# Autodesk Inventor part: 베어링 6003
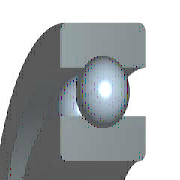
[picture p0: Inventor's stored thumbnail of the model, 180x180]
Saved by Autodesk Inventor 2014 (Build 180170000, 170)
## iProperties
Created: 2012-02
Part Number: 베어링 6003
Material: 강철, 연강
Description: 깊은 그루브 볼 베어링
Document SubType Name: Modeling
Standard: KS B 2023
Designer: mduedu
Standards Organization: KS
Language: ko-KR
Size Designation: 6003 - 17 x 35 x 10
Categories: <MemberInstance><Categories><Category DisplayName="샤프트 부품" InternalName="7f7aeb1f-a693-4053-b835-cee3144e0d98" Mnemonic="SHFT"><Category DisplayName="베어링" Inter
Density: 7.86 g/cm^3
Appearance: Turquoise
Mass: 35.231 g
Surface Area: 48.7538 cm^2
Volume: 4.48231 cm^3
IsCustomPart: 1
Author: mduedu
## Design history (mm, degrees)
sketch "스케치" dims "d0" = 4.68 (= -0.26 x WD + 0.26 x BD)
  geometry: L1 (2.66, 13)-(7.34, 13); L2 (5, 13)-(5, 10.66); L3 (5, 13)-(5, 15.34); L4 (3.261, 11.434)-(0, 11.434); L5 (0, 8.5)-(10, 8.5); L6 (3.261, 14.566)-(0, 14.566); L7 (0, 17.5)-(10, 17.5); L8 (10, 8.5)-(10, 11.434); L9 (6.739, 11.434)-(10, 11.434); L10 (6.739, 14.566)-(10, 14.566); L11 (10, 17.5)-(10, 14.566); L12 (-1.4, 0)-(8.4, 0) reference; L13 (0, -0.3)-(0, 5.3) reference
  constraints: 22 end point, 4 point on line, 2 collinear, 2 perpendicular, 2 symmetric about line, 1 midpoint, 1 parallel, 14 other
  dimensions: "d9" = 17 diameter of L5 L12 (= WD); "d11" = 35 diameter of L7 L12 (= BD); "d12" = 10 distance between parallel lines of L8 L13 (= KB); "d13" = 22.868 diameter of L9 L12 (= 0.326 x BD + 0.674 x WD)
revolve "본체" stored, may be unused: angle "d6" = 90 deg
revolve "볼" stored, may be unused: angle "d7" = 90 deg
pattern_circular "IDS_ARRAYBALL[SIMPL:T]" dims angle "d3" = 360 deg
body "Solid1"
fillet "모깎기1" dims "d1" = 0.3 (= KRS)
other parameters: "WD" = 17 [user parameter; used in 5 equation terms], "BD" = 35 [user parameter; used in 5 equation terms], "KB" = 10 [user parameter; used in 1 equation term], "KRS" = 0.3 [user parameter; used in 1 equation term], "d4" = 0, "d5" = 0, "d8" = 0, "d14" = 0, "d15" = 0, "BBA" = 0 [user parameter], "BC0" = 3250000 [user parameter], "BC" = 6050000 [user parameter], "BR" = 17.5 (= 0.5 x BD) [user parameter], "WR" = 8.5 (= 0.5 x WD) [user parameter]
